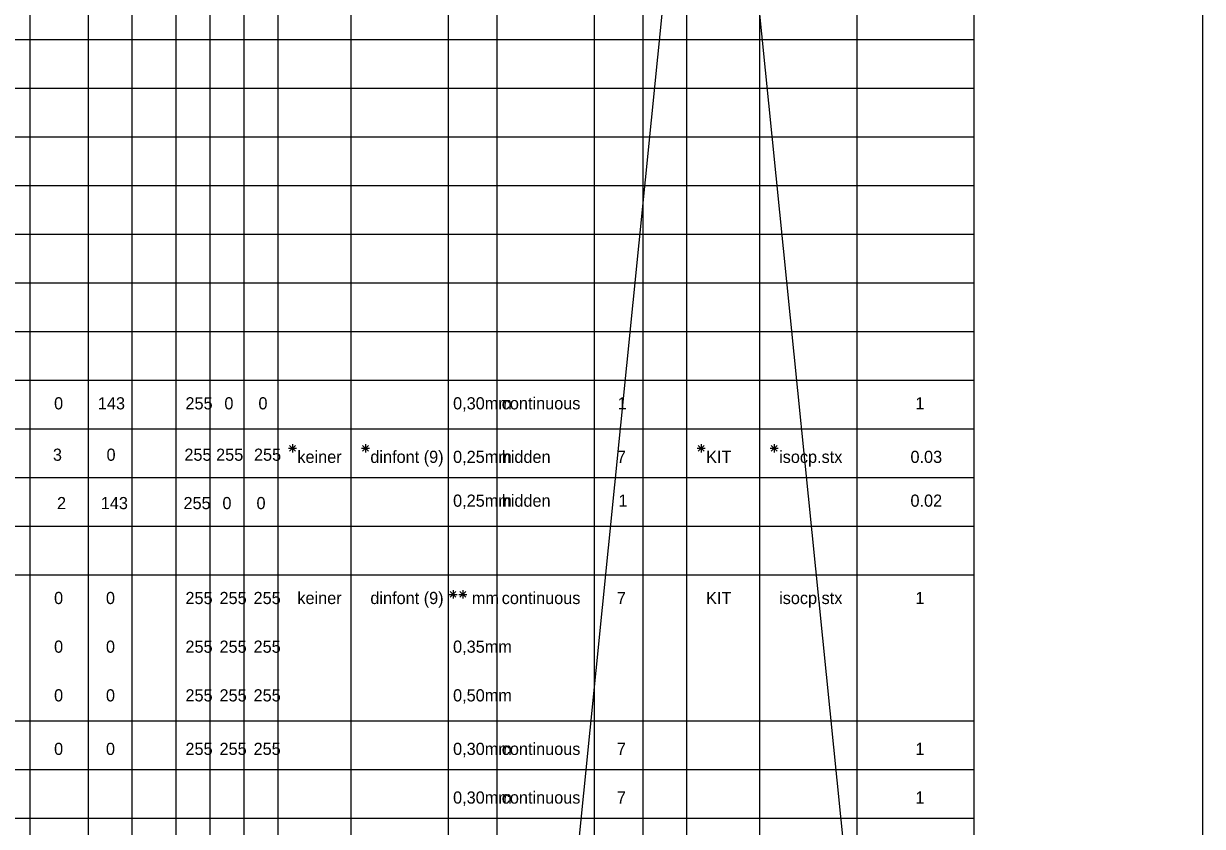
# Model space of a CAD drawing. Extents: x -14.5 to 23.8, y -56.3 to 8.
# Drawn here: x 11.64 to 23.75, y -40.08 to -31.84 of the extents above; entities that cross this region are included whole.
import ezdxf

# ---------------------------------------------------------------- set-up
doc = ezdxf.new("R2010")
doc.units = 0
doc.layers.add('Default', color=7, linetype='Continuous')
doc.layers.add('Default_DWG', color=7, linetype='Continuous')

msp = doc.modelspace()

# ---------------------------------------------------------------- linework, layer by layer
at = {"layer": 'Default'}
for p, q in [((16, 0), (16, -48)), ((21.4, 0), (16, -53.5)), ((21.4, -53.5), (16, 0)), ((21.4, 0), (21.4, -53.5)), ((23.75, 0), (23.75, -53.5)), ((11.7, -0.35), (11.7, -44.5)), ((12.3, -0.35), (12.3, -44.5)), ((12.75, -0.35), (12.75, -44.5)), ((13.2, -0.35), (13.2, -44.5)), ((14.25, -0.35), (14.25, -48)), ((15, -0.35), (15, -48)), ((13.55, -0.75), (13.55, -44.5)), ((13.9, -0.75), (13.9, -44.5)), ((0, -32), (16, -32)), ((0, -32.5), (16, -32.5)), ((0, -33), (16, -33)), ((0, -33.5), (16, -33.5)), ((0, -34), (16, -34)), ((0, -34.5), (16, -34.5)), ((0, -35), (16, -35)), ((0, -35.5), (16, -35.5)), ((0, -36), (16, -36)), ((14.358, -36.2), (14.442, -36.2)), ((14.37, -36.17), (14.43, -36.23)), ((14.43, -36.17), (14.37, -36.23)), ((14.4, -36.158), (14.4, -36.242)), ((15.108, -36.2), (15.192, -36.2)), ((15.12, -36.17), (15.18, -36.23)), ((15.18, -36.17), (15.12, -36.23)), ((15.15, -36.158), (15.15, -36.242)), ((0, -36.5), (16, -36.5)), ((0, -37), (16, -37)), ((0, -37.5), (16, -37.5)), ((0, -39), (16, -39)), ((0, -39.5), (16, -39.5)), ((0, -40), (16, -40))]:
    msp.add_line(p, q, dxfattribs=at)
at = {"layer": 'Default_DWG'}
for p, q in [((20.2, 0), (20.2, -48)), ((16.5, -0.35), (16.5, -48)), ((17.5, -0.35), (17.5, -48)), ((18, -0.35), (18, -48)), ((18.45, -0.35), (18.45, -48)), ((19.2, -0.35), (19.2, -48)), ((16, -32), (21.4, -32)), ((16, -32.5), (21.4, -32.5)), ((16, -33), (21.4, -33)), ((16, -33.5), (21.4, -33.5)), ((16, -34), (21.4, -34)), ((16, -34.5), (21.4, -34.5)), ((16, -35), (21.4, -35)), ((16, -35.5), (21.4, -35.5)), ((16, -36), (21.4, -36)), ((18.558, -36.2), (18.642, -36.2)), ((18.57, -36.17), (18.63, -36.23)), ((18.63, -36.17), (18.57, -36.23)), ((18.6, -36.158), (18.6, -36.242)), ((19.308, -36.2), (19.392, -36.2)), ((19.32, -36.17), (19.38, -36.23)), ((19.38, -36.17), (19.32, -36.23)), ((19.35, -36.158), (19.35, -36.242)), ((16, -36.5), (21.4, -36.5)), ((16, -37), (21.4, -37)), ((16, -37.5), (21.4, -37.5)), ((16.02, -37.67), (16.08, -37.73)), ((16.08, -37.67), (16.02, -37.73)), ((16.05, -37.658), (16.05, -37.742)), ((16.12, -37.67), (16.18, -37.73)), ((16.18, -37.67), (16.12, -37.73)), ((16.15, -37.658), (16.15, -37.742)), ((16.008, -37.7), (16.092, -37.7)), ((16.108, -37.7), (16.192, -37.7)), ((16, -39), (21.4, -39)), ((16, -39.5), (21.4, -39.5)), ((16, -40), (21.4, -40))]:
    msp.add_line(p, q, dxfattribs=at)

# ---------------------------------------------------------------- texts
at = {"layer": 'Default'}
for s, p in [('0', (11.95, -35.8)), ('143', (12.4, -35.8)), ('255', (13.3, -35.8)), ('0', (13.7, -35.8)), ('0', (14.05, -35.8)), ('3', (11.938, -36.328)), ('0', (12.489, -36.328)), ('255', (13.289, -36.328)), ('255', (13.615, -36.328)), ('255', (14.004, -36.328)), ('keiner', (14.45, -36.35)), ('dinfont (9)', (15.2, -36.35)), ('2', (11.98, -36.825)), ('143', (12.43, -36.825)), ('255', (13.28, -36.825)), ('0', (13.68, -36.825)), ('0', (14.03, -36.825)), ('keiner', (14.45, -37.8)), ('dinfont (9)', (15.2, -37.8)), ('0', (11.95, -37.8)), ('0', (12.483, -37.8)), ('255', (13.3, -37.8)), ('255', (13.65, -37.8)), ('255', (14, -37.8)), ('0', (11.95, -38.3)), ('0', (12.483, -38.3)), ('255', (13.3, -38.3)), ('255', (13.65, -38.3)), ('255', (14, -38.3)), ('0', (11.95, -38.8)), ('0', (12.483, -38.8)), ('255', (13.3, -38.8)), ('255', (13.65, -38.8)), ('255', (14, -38.8)), ('0', (11.95, -39.35)), ('0', (12.483, -39.35)), ('255', (13.3, -39.35)), ('255', (13.65, -39.35)), ('255', (14, -39.35))]:
    msp.add_text(s, height=0.125, dxfattribs=at).set_placement(p)
at = {"layer": 'Default_DWG'}
for s, p in [('0,30mm', (16.05, -35.8)), ('continuous', (16.55, -35.8)), ('1', (17.742, -35.8)), ('1', (20.8, -35.8)), ('hidden', (16.55, -36.35)), ('isocp.stx', (19.4, -36.35)), ('0,25mm', (16.05, -36.35)), ('7', (17.733, -36.35)), ('KIT', (18.65, -36.35)), ('0.03', (20.75, -36.35)), ('0,25mm', (16.05, -36.8)), ('hidden', (16.55, -36.8)), ('1', (17.75, -36.8)), ('0.02', (20.75, -36.8)), ('continuous', (16.55, -37.8)), ('isocp.stx', (19.4, -37.8)), ('  mm', (16.15, -37.8)), ('7', (17.733, -37.8)), ('KIT', (18.65, -37.8)), ('1', (20.8, -37.8)), ('0,35mm', (16.05, -38.3)), ('0,50mm', (16.05, -38.8)), ('0,30mm', (16.05, -39.35)), ('continuous', (16.55, -39.35)), ('7', (17.733, -39.35)), ('1', (20.8, -39.35)), ('0,30mm', (16.05, -39.85)), ('continuous', (16.55, -39.85)), ('7', (17.733, -39.85)), ('1', (20.8, -39.85))]:
    msp.add_text(s, height=0.125, dxfattribs=at).set_placement(p)

doc.saveas('drawing.dxf')
